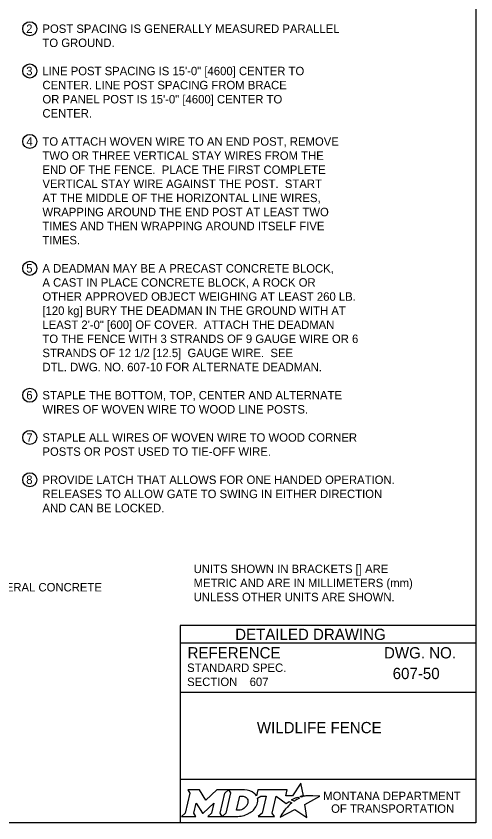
# Model space of a CAD drawing. Extents: x 49991.4 to 50021, y 49987.6 to 50011.4.
# Drawn here: x 50013.49 to 50016.75, y 49987.8 to 49993.52 of the extents above; entities that cross this region are included whole.
import ezdxf

# ---------------------------------------------------------------- set-up
doc = ezdxf.new("R2010")
doc.units = 0
for name, color, linetype in [('Default', 7, 'Continuous'), ('Level 1', 7, 'Continuous'), ('Level 2', 7, 'Continuous'), ('Level 5', 7, 'Continuous')]:
    doc.layers.add(name, color=color, linetype=linetype)

msp = doc.modelspace()

# ---------------------------------------------------------------- linework, layer by layer
at = {"layer": 'Default'}
for points in [[(50015.5126, 49987.9811), (50015.5023, 49987.9867), (50015.5139, 49987.9895), (50015.5255, 49987.9915), (50015.5081, 49988.0816), (50015.4486, 49987.9903), (50015.4013, 49987.9896), (50015.4116, 49988.0337), (50015.2024, 49988.0338), (50015.1923, 49987.9913), (50015.1865, 49987.9996)], [(50014.7056, 49988.0338), (50014.7197, 49988.0104), (50014.6862, 49987.8671), (50014.6605, 49987.8446), (50014.7621, 49987.8446), (50014.7486, 49987.8674), (50014.7648, 49987.9375), (50014.8085, 49987.8685), (50014.8138, 49987.8685), (50014.8889, 49987.938), (50014.8725, 49987.8669), (50014.8478, 49987.8449), (50014.9494, 49987.8449), (50014.9356, 49987.8682), (50014.9688, 49988.0106)], [(50014.9688, 49988.0106), (50014.9941, 49988.0338), (50014.9117, 49988.0338), (50014.8321, 49987.9608), (50014.7876, 49988.0335), (50014.7056, 49988.0338)], [(50015.1077, 49988.0338), (50014.9941, 49988.0338), (50015.0088, 49988.0109), (50014.9749, 49987.8671), (50014.9494, 49987.8449), (50015.06, 49987.8449)], [(50015.1317, 49987.9471), (50015.1305, 49987.939), (50015.1273, 49987.9297), (50015.1231, 49987.9215), (50015.1175, 49987.914), (50015.111, 49987.9071), (50015.1031, 49987.9008), (50015.0948, 49987.8961), (50015.0857, 49987.8922), (50015.0766, 49987.8899), (50015.0674, 49987.889), (50015.0515, 49987.889), (50015.0751, 49987.989), (50015.0911, 49987.989), (50015.0987, 49987.9884), (50015.1063, 49987.9865), (50015.1129, 49987.9835), (50015.119, 49987.9793), (50015.1238, 49987.9743), (50015.1275, 49987.9683), (50015.1302, 49987.9621), (50015.1318, 49987.9547), (50015.1318, 49987.9517), (50015.1317, 49987.9471)], [(50015.1991, 49987.9747), (50015.2237, 49987.9878), (50015.2606, 49987.9878), (50015.232, 49987.8673), (50015.2045, 49987.8446), (50015.3207, 49987.8446), (50015.3037, 49987.8675), (50015.3319, 49987.9877), (50015.4032, 49987.936), (50015.4243, 49987.9511), (50015.444, 49987.9402)], [(50015.3882, 49987.8843), (50015.3729, 49987.8599), (50015.3682, 49987.8524), (50015.3624, 49987.8438), (50015.3601, 49987.8395), (50015.4654, 49987.8926), (50015.5493, 49987.8375), (50015.5362, 49987.9302), (50015.6431, 49987.9886), (50015.5938, 49987.9894), (50015.5637, 49987.9898), (50015.5429, 49987.9901), (50015.5361, 49987.9886), (50015.5312, 49987.9874), (50015.5228, 49987.9851), (50015.5126, 49987.9811)], [(50015.4622, 49987.9535), (50015.4598, 49987.9518), (50015.4415, 49987.9614), (50015.4518, 49987.9671), (50015.4559, 49987.9693), (50015.4645, 49987.9733), (50015.4702, 49987.9759), (50015.4781, 49987.9789), (50015.4854, 49987.9816), (50015.4972, 49987.9742), (50015.4932, 49987.9721), (50015.4886, 49987.9696), (50015.4844, 49987.9674), (50015.4794, 49987.9645), (50015.4775, 49987.9634), (50015.4748, 49987.9618), (50015.4723, 49987.9604), (50015.47, 49987.9588), (50015.4674, 49987.957), (50015.4647, 49987.9552), (50015.4622, 49987.9535)], [(50015.1057, 49987.8522), (50015.1141, 49987.8548), (50015.1271, 49987.8602), (50015.1475, 49987.8712)], [(50015.4021, 49987.9004), (50015.4021, 49987.9004)]]:
    msp.add_lwpolyline(points, dxfattribs=at)
for centre, radius, start, end in [((50015.1308, 49987.9554), 0.0709, 339.5329, 15.8582), ((50015.0868, 49987.9727), 0.1183, 300.9103, 339.1383)]:
    msp.add_arc(centre, radius, start, end, dxfattribs=at)
for centre, major_axis, ratio, start_param, end_param in [((50015.1056, 49987.9864), (0.0834, -0.0037), 0.568097, 0.61298, 1.570796), ((50015.1612, 49987.9937), (0.0361, -0.0295), 0.469099, 1.225588, 1.570796), ((50015.4119, 49987.9106), (-0.0098, -0.0102), 0.016458, 3.141593, 6.279097), ((50015.4329, 49987.9305), (-0.0112, -0.0097), 0.021651, 3.157348, 6.283185), ((50015.0603, 49987.9932), (0, 0.1484), 0.987302, 3.139398, 3.456847), ((50015.3952, 49987.8923), (-0.00694, -0.00806), 0.008222, 0, 3.137361)]:
    msp.add_ellipse(centre, major_axis=major_axis, ratio=ratio, start_param=start_param, end_param=end_param, dxfattribs=at)
at = {"layer": 'Level 1'}
msp.add_lwpolyline([(49999.3835, 49998.9992), (50016.7501, 49998.9992), (50016.7501, 49987.7988), (49999.3835, 49987.7988)], close=True, dxfattribs=at)
at = {"layer": 'Level 2'}
for centre in [(50013.5833, 49993.4328), (50013.5833, 49993.1328), (50013.5833, 49992.6328), (50013.5833, 49991.7328), (50013.5833, 49990.8328), (50013.5833, 49990.5328), (50013.5833, 49990.2328)]:
    msp.add_circle(centre, 0.05, dxfattribs=at)
at = {"layer": 'Level 5'}
for p, q in [((50016.7501, 49989.1988), (50014.6501, 49989.1988)), ((50014.6501, 49989.1988), (50014.6501, 49987.7988)), ((50016.7501, 49989.0738), (50014.6501, 49989.0738)), ((50016.3862, 49988.8587), (50016.3862, 49988.8587)), ((50015.1444, 49988.7993), (50015.1444, 49988.7993)), ((50016.7501, 49988.7238), (50014.6501, 49988.7238)), ((50015.7001, 49988.4747), (50015.7001, 49988.4747)), ((50016.7501, 49988.1057), (50014.6501, 49988.1057))]:
    msp.add_line(p, q, dxfattribs=at)

# ---------------------------------------------------------------- texts
at = {"layer": 'Default'}
for s, p in [('MONTANA DEPARTMENT', (50015.6663, 49987.96)), ('OF TRANSPORTATION', (50015.7225, 49987.87))]:
    msp.add_text(s, height=0.06, dxfattribs=at).set_placement(p)
at = {"layer": 'Level 2'}
for s, height, p in [('2', 0.06, (50013.5581, 49993.4028)), ('POST SPACING IS GENERALLY MEASURED PARALLEL', 0.06, (50013.6733, 49993.4028)), ('TO GROUND.', 0.06, (50013.6733, 49993.3028)), ('LINE POST SPACING IS 15\'-0" [4600] CENTER TO ', 0.06, (50013.6733, 49993.1028)), ('3', 0.06, (50013.5581, 49993.1028)), ('CENTER. LINE POST SPACING FROM BRACE ', 0.06, (50013.6733, 49993.0028)), ('OR PANEL POST IS 15\'-0" [4600] CENTER TO ', 0.06, (50013.6733, 49992.9028)), ('CENTER.', 0.06, (50013.6733, 49992.8028)), ('4', 0.06, (50013.5593, 49992.6028)), ('TO ATTACH WOVEN WIRE TO AN END POST, REMOVE', 0.06, (50013.6733, 49992.6028)), ('TWO OR THREE VERTICAL STAY WIRES FROM THE', 0.06, (50013.6733, 49992.5028)), ('END OF THE FENCE.  PLACE THE FIRST COMPLETE', 0.06, (50013.6733, 49992.4028)), ('VERTICAL STAY WIRE AGAINST THE POST.  START', 0.06, (50013.6733, 49992.3028)), ('AT THE MIDDLE OF THE HORIZONTAL LINE WIRES,', 0.06, (50013.6733, 49992.2028)), ('WRAPPING AROUND THE END POST AT LEAST TWO', 0.06, (50013.6733, 49992.1028)), ('TIMES AND THEN WRAPPING AROUND ITSELF FIVE', 0.06, (50013.6733, 49992.0028)), ('TIMES.', 0.06, (50013.6733, 49991.9028)), ('5', 0.06, (50013.5583, 49991.7028)), ('A DEADMAN MAY BE A PRECAST CONCRETE BLOCK,', 0.06, (50013.6733, 49991.7028)), ('A CAST IN PLACE CONCRETE BLOCK, A ROCK OR', 0.06, (50013.6733, 49991.6028)), ('OTHER APPROVED OBJECT WEIGHING AT LEAST 260 LB.', 0.06, (50013.6733, 49991.5028)), ('[120 kg] BURY THE DEADMAN IN THE GROUND WITH AT ', 0.06, (50013.6733, 49991.4028)), ('LEAST 2\'-0" [600] OF COVER.  ATTACH THE DEADMAN ', 0.06, (50013.6733, 49991.3028)), ('TO THE FENCE WITH 3 STRANDS OF 9 GAUGE WIRE OR 6', 0.06, (50013.6733, 49991.2028)), ('STRANDS OF 12 1/2 [12.5]  GAUGE WIRE.  SEE ', 0.06, (50013.6733, 49991.1028)), ('DTL. DWG. NO. 607-10 FOR ALTERNATE DEADMAN. ', 0.06, (50013.6733, 49991.0028)), ('6', 0.06, (50013.5587, 49990.8028)), ('STAPLE THE BOTTOM, TOP, CENTER AND ALTERNATE', 0.06, (50013.6733, 49990.8028)), ('WIRES OF WOVEN WIRE TO WOOD LINE POSTS.', 0.06, (50013.6733, 49990.7028)), ('7', 0.06, (50013.5595, 49990.5028)), ('STAPLE ALL WIRES OF WOVEN WIRE TO WOOD CORNER', 0.06, (50013.6733, 49990.5028)), ('POSTS OR POST USED TO TIE-OFF WIRE.', 0.06, (50013.6733, 49990.4028)), ('8', 0.06, (50013.5583, 49990.2028)), ('PROVIDE LATCH THAT ALLOWS FOR ONE HANDED OPERATION.', 0.06, (50013.6733, 49990.2028)), ('RELEASES TO ALLOW GATE TO SWING IN EITHER DIRECTION', 0.06, (50013.6733, 49990.1028)), ('AND CAN BE LOCKED.', 0.06, (50013.6733, 49990.0028)), ('UNITS SHOWN IN BRACKETS [] ARE ', 0.06, (50014.7466, 49989.571)), ('METRIC AND ARE IN MILLIMETERS (mm) ', 0.06, (50014.7466, 49989.471)), ('CLASS GENERAL CONCRETE', 0.060003, (50012.9539, 49989.4406)), ('UNLESS OTHER UNITS ARE SHOWN.', 0.06, (50014.7466, 49989.371)), ('607-50', 0.08, (50016.1596, 49988.8187)), ('607', 0.06, (50015.1444, 49988.7693)), ('WILDLIFE FENCE', 0.08, (50015.1955, 49988.4347))]:
    msp.add_text(s, height=height, dxfattribs=at).set_placement(p)
at = {"layer": 'Level 5'}
for s, height, p in [('DETAILED DRAWING', 0.0799, (50015.0418, 49989.0963)), ('REFERENCE', 0.08, (50014.7037, 49988.9654)), ('DWG. NO.', 0.08, (50016.0979, 49988.9654)), ('STANDARD SPEC.', 0.06, (50014.7004, 49988.8694)), ('SECTION', 0.06, (50014.7004, 49988.7694))]:
    msp.add_text(s, height=height, dxfattribs=at).set_placement(p)

doc.saveas('drawing.dxf')
